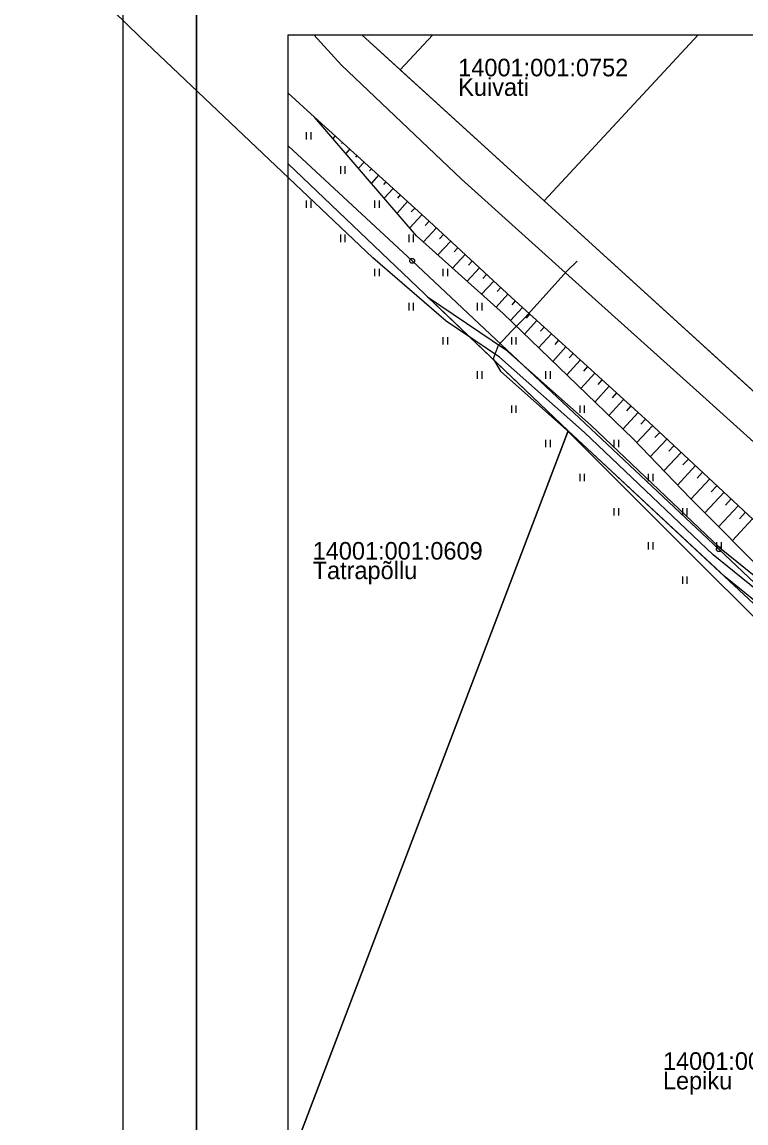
# Model space of a CAD drawing. Extents: x 567864 to 568657, y 6579839 to 6580994.
# Drawn here: x 568233.7 to 568307.8, y 6580491.9 to 6580604.7 of the extents above; entities that cross this region are included whole.
import ezdxf

# ---------------------------------------------------------------- set-up
doc = ezdxf.new("R2010")
doc.units = 0
for name, color, linetype in [('HALJASTUS', 7, 'Continuous'), ('KASUTUSALA', 7, 'Continuous'), ('MPKAABEL', 7, 'Continuous'), ('MPOHULIIN', 7, 'Continuous'), ('PIIR', 7, 'Continuous'), ('POST', 7, 'Continuous'), ('PR_SIDE', 7, 'Continuous'), ('RELJEEF', 7, 'Continuous'), ('TEE', 7, 'Continuous'), ('VORMISTUS_2', 7, 'Continuous')]:
    doc.layers.add(name, color=color, linetype=linetype)

msp = doc.modelspace()

# ---------------------------------------------------------------- linework, layer by layer
at = {"layer": 'HALJASTUS'}
for p, q in [((568262.77, 6580593.38), (568262.77, 6580592.62)), ((568263.23, 6580593.38), (568263.23, 6580592.62)), ((568266.27, 6580589.88), (568266.27, 6580589.12)), ((568266.73, 6580589.88), (568266.73, 6580589.12)), ((568262.77, 6580586.38), (568262.77, 6580585.62)), ((568263.23, 6580586.38), (568263.23, 6580585.62)), ((568269.77, 6580586.38), (568269.77, 6580585.62)), ((568270.23, 6580586.38), (568270.23, 6580585.62)), ((568266.27, 6580582.88), (568266.27, 6580582.12)), ((568266.73, 6580582.88), (568266.73, 6580582.12)), ((568273.27, 6580582.88), (568273.27, 6580582.12)), ((568273.73, 6580582.88), (568273.73, 6580582.12)), ((568269.77, 6580579.38), (568269.77, 6580578.62)), ((568270.23, 6580579.38), (568270.23, 6580578.62)), ((568276.77, 6580579.38), (568276.77, 6580578.62)), ((568277.23, 6580579.38), (568277.23, 6580578.62)), ((568273.27, 6580575.88), (568273.27, 6580575.12)), ((568273.73, 6580575.88), (568273.73, 6580575.12)), ((568280.27, 6580575.88), (568280.27, 6580575.12)), ((568280.73, 6580575.88), (568280.73, 6580575.12)), ((568276.77, 6580572.38), (568276.77, 6580571.62)), ((568277.23, 6580572.38), (568277.23, 6580571.62)), ((568283.77, 6580572.38), (568283.77, 6580571.62)), ((568284.23, 6580572.38), (568284.23, 6580571.62)), ((568280.27, 6580568.88), (568280.27, 6580568.12)), ((568280.73, 6580568.88), (568280.73, 6580568.12)), ((568287.27, 6580568.88), (568287.27, 6580568.12)), ((568287.73, 6580568.88), (568287.73, 6580568.12)), ((568283.77, 6580565.38), (568283.77, 6580564.62)), ((568284.23, 6580565.38), (568284.23, 6580564.62)), ((568290.77, 6580565.38), (568290.77, 6580564.62)), ((568291.23, 6580565.38), (568291.23, 6580564.62)), ((568287.27, 6580561.88), (568287.27, 6580561.12)), ((568287.73, 6580561.88), (568287.73, 6580561.12)), ((568294.27, 6580561.88), (568294.27, 6580561.12)), ((568294.73, 6580561.88), (568294.73, 6580561.12)), ((568290.77, 6580558.38), (568290.77, 6580557.62)), ((568291.23, 6580558.38), (568291.23, 6580557.62)), ((568297.77, 6580558.38), (568297.77, 6580557.62)), ((568298.23, 6580558.38), (568298.23, 6580557.62)), ((568294.27, 6580554.88), (568294.27, 6580554.12)), ((568294.73, 6580554.88), (568294.73, 6580554.12)), ((568301.27, 6580554.88), (568301.27, 6580554.12)), ((568301.73, 6580554.88), (568301.73, 6580554.12)), ((568297.77, 6580551.38), (568297.77, 6580550.62)), ((568298.23, 6580551.38), (568298.23, 6580550.62)), ((568304.77, 6580551.38), (568304.77, 6580550.62)), ((568305.23, 6580551.38), (568305.23, 6580550.62)), ((568301.27, 6580547.88), (568301.27, 6580547.12)), ((568301.73, 6580547.88), (568301.73, 6580547.12))]:
    msp.add_line(p, q, dxfattribs=at)
at = {"layer": 'KASUTUSALA'}
msp.add_lwpolyline([(568371.56, 6580487.01), (568366.82, 6580493.74), (568336.54, 6580520.89), (568334.37, 6580522.89), (568333.16, 6580524.02), (568322.19, 6580534.42), (568305.67, 6580547.79), (568289.57, 6580562.8), (568275.19, 6580576.52), (568283.17, 6580571.11), (568291.95, 6580563.33), (568305.08, 6580550.84), (568323.51, 6580535.93), (568334.54, 6580525.48), (568335.07, 6580524.98), (568344.93, 6580533.71), (568344.98, 6580533.67), (568346.42, 6580532.36), (568336.55, 6580523.61), (568337.05, 6580523.13), (568337.88, 6580522.37), (568368.32, 6580495.08), (568373.24, 6580488.09)], dxfattribs=at)
at = {"layer": 'MPKAABEL'}
msp.add_lwpolyline([(568290.51, 6580580.15), (568289.47, 6580579.17), (568285.16, 6580574.37), (568283.84, 6580573.07), (568282.41, 6580571.53), (568281.92, 6580570.15), (568282.67, 6580568.89), (568289.46, 6580562.85), (568299.87, 6580552.42), (568311.62, 6580540.71), (568323.73, 6580528.68), (568334.96, 6580518.16), (568345.24, 6580508.32), (568353.21, 6580500.74), (568358.87, 6580494.79), (568362.88, 6580490.81), (568367.26, 6580487.78), (568369.74, 6580485.8), (568369.72, 6580484.3), (568368.69, 6580483.14), (568367.08, 6580481.93), (568366.32, 6580481.93), (568366.01, 6580481.86)], dxfattribs=at)
at = {"layer": 'MPOHULIIN'}
msp.add_lwpolyline([(568335.69, 6580521.66), (568305, 6580550.67), (568273.62, 6580580.19), (568260.93, 6580591.97)], dxfattribs=at)
at = {"layer": 'PIIR'}
for points in [[(568268.46, 6580603.35), (568287.11, 6580586.34), (568330.81, 6580546.53), (568384.68, 6580497.48)], [(568275.73, 6580603.35), (568272.4, 6580599.76), (568268.46, 6580603.35)], [(568302.89, 6580603.35), (568287.11, 6580586.34), (568272.4, 6580599.76), (568275.73, 6580603.35)], [(568383.76, 6580603.35), (568370.95, 6580562.05), (568344.98, 6580533.67), (568287.11, 6580586.34), (568302.89, 6580603.35)], [(568384.68, 6580474.14), (568373.5, 6580484.56), (568289.57, 6580562.8), (568260.93, 6580590.14)], [(568260.93, 6580590.14), (568289.57, 6580562.8), (568260.93, 6580487.5)], [(568260.93, 6580487.5), (568289.57, 6580562.8), (568373.5, 6580484.56), (568310.3, 6580445.85)]]:
    msp.add_lwpolyline(points, dxfattribs=at)
at = {"layer": 'POST'}
for centre in [(568273.62, 6580580.19), (568305, 6580550.67)]:
    msp.add_circle(centre, 0.25, dxfattribs=at)
at = {"layer": 'PR_SIDE'}
msp.add_lwpolyline([(568372.77, 6580480.66), (568372.77, 6580480.66), (568372.77, 6580480.66), (568373.4, 6580481.36), (568374.25, 6580482.51), (568374.05, 6580484.04), (568373.82, 6580485.15), (568372.4, 6580487.55), (568367.57, 6580494.41), (568337.21, 6580521.63), (568335.06, 6580523.62), (568333.85, 6580524.75), (568322.86, 6580535.18), (568304.42, 6580550.09), (568291.27, 6580562.6), (568282.56, 6580570.32), (568277.09, 6580574.03), (568269.58, 6580580.5), (568245.73, 6580603.12), (568233.69, 6580614.91)], dxfattribs=at)
at = {"layer": 'RELJEEF'}
for p, q in [((568264.26, 6580594.34), (568264.19, 6580594.26)), ((568265, 6580593.66), (568264.95, 6580593.61)), ((568265.74, 6580592.99), (568265.5, 6580592.73)), ((568266.48, 6580592.32), (568266.38, 6580592.21)), ((568267.22, 6580591.65), (568266.81, 6580591.2)), ((568267.96, 6580590.97), (568267.81, 6580590.81)), ((568268.7, 6580590.3), (568268.13, 6580589.67)), ((568269.44, 6580589.63), (568269.24, 6580589.41)), ((568270.18, 6580588.96), (568269.44, 6580588.14)), ((568270.92, 6580588.28), (568270.67, 6580588.01)), ((568271.66, 6580587.61), (568270.75, 6580586.61)), ((568272.4, 6580586.94), (568272.1, 6580586.61)), ((568273.14, 6580586.27), (568272.07, 6580585.08)), ((568274.62, 6580584.92), (568273.38, 6580583.56)), ((568273.88, 6580585.59), (568273.53, 6580585.21)), ((568276.09, 6580583.57), (568274.76, 6580582.13)), ((568275.36, 6580584.25), (568274.96, 6580583.82)), ((568276.83, 6580582.89), (568276.43, 6580582.46)), ((568277.56, 6580582.21), (568276.25, 6580580.8)), ((568278.29, 6580581.53), (568277.9, 6580581.11)), ((568279.03, 6580580.85), (568277.74, 6580579.46)), ((568279.76, 6580580.17), (568279.38, 6580579.76)), ((568280.49, 6580579.49), (568279.23, 6580578.12)), ((568281.96, 6580578.13), (568280.72, 6580576.79)), ((568281.22, 6580578.81), (568280.85, 6580578.4)), ((568283.42, 6580576.77), (568282.21, 6580575.45)), ((568282.69, 6580577.45), (568282.32, 6580577.05)), ((568284.16, 6580576.09), (568283.8, 6580575.7)), ((568284.9, 6580575.42), (568283.68, 6580574.08)), ((568285.64, 6580574.75), (568285.27, 6580574.34)), ((568286.38, 6580574.07), (568285.12, 6580572.69)), ((568287.12, 6580573.4), (568286.74, 6580572.98)), ((568287.86, 6580572.73), (568286.56, 6580571.3)), ((568289.34, 6580571.38), (568288, 6580569.9)), ((568288.6, 6580572.06), (568288.2, 6580571.62)), ((568290.82, 6580570.04), (568289.44, 6580568.51)), ((568290.08, 6580570.71), (568289.67, 6580570.26)), ((568291.56, 6580569.37), (568291.14, 6580568.9)), ((568292.3, 6580568.69), (568290.87, 6580567.12)), ((568293.04, 6580568.02), (568292.61, 6580567.54)), ((568293.78, 6580567.35), (568292.31, 6580565.73)), ((568294.52, 6580566.68), (568294.07, 6580566.18)), ((568295.26, 6580566), (568293.75, 6580564.34)), ((568296.74, 6580564.66), (568295.19, 6580562.95)), ((568296, 6580565.33), (568295.54, 6580564.82)), ((568298.22, 6580563.31), (568296.59, 6580561.56)), ((568297.48, 6580563.98), (568297.01, 6580563.47)), ((568298.95, 6580562.63), (568298.45, 6580562.09)), ((568299.68, 6580561.94), (568297.98, 6580560.12)), ((568300.41, 6580561.26), (568299.89, 6580560.7)), ((568301.14, 6580560.58), (568299.37, 6580558.68)), ((568301.88, 6580559.9), (568301.33, 6580559.32)), ((568302.61, 6580559.22), (568300.76, 6580557.23)), ((568304.07, 6580557.86), (568302.15, 6580555.79)), ((568303.34, 6580558.54), (568302.77, 6580557.93)), ((568305.54, 6580556.49), (568303.56, 6580554.38)), ((568304.8, 6580557.17), (568304.22, 6580556.55)), ((568306.27, 6580555.81), (568305.67, 6580555.17)), ((568307, 6580555.13), (568304.98, 6580552.96)), ((568307.73, 6580554.45), (568307.12, 6580553.79)), ((568308.46, 6580553.77), (568306.39, 6580551.54))]:
    msp.add_line(p, q, dxfattribs=at)
msp.add_lwpolyline([(568310.42, 6580547.5), (568302.1, 6580555.85), (568296.22, 6580561.96), (568282.93, 6580574.8), (568274.07, 6580582.75), (568263.63, 6580594.9)], dxfattribs=at)
at = {"layer": 'TEE'}
for points in [[(568384.68, 6580492.57), (568380.78, 6580496.19), (568368.5, 6580507.85), (568359.52, 6580516.22), (568354.33, 6580521.19), (568352.36, 6580522.29), (568341.44, 6580532.14), (568331.96, 6580540.8), (568322.6, 6580549.12), (568312.08, 6580558.49), (568303.36, 6580566.33), (568291.02, 6580577.44), (568278.67, 6580588.56), (568266.39, 6580600.24), (568263.55, 6580603.35)], [(568376.41, 6580491.21), (568374.68, 6580493.82), (568369.68, 6580498.66), (568354.03, 6580512.91), (568337.06, 6580528.03), (568327.84, 6580536.25), (568318.37, 6580544.73), (568308.51, 6580553.72), (568297.84, 6580563.66), (568283.77, 6580576.45), (568275.34, 6580584.27), (568263.63, 6580594.9), (568260.93, 6580597.38)]]:
    msp.add_lwpolyline(points, dxfattribs=at)
at = {"layer": 'VORMISTUS_2'}
for points in [[(568244.05, 6580640.85), (568401.55, 6580640.85), (568401.55, 6580418.1), (568244.05, 6580418.1)], [(568251.55, 6580426.35), (568394.05, 6580426.35), (568394.05, 6580632.6), (568251.55, 6580632.6)], [(568251.55, 6580632.6), (568394.05, 6580632.6), (568394.05, 6580426.35), (568251.55, 6580426.35)], [(568384.68, 6580445.85), (568260.93, 6580445.85), (568260.93, 6580603.35), (568384.68, 6580603.35)]]:
    msp.add_lwpolyline(points, close=True, dxfattribs=at)

# ---------------------------------------------------------------- texts
at = {"layer": 'PIIR'}
for s, p in [('14001:001:0752', (568278.33, 6580599.09)), ('Kuivati', (568278.33, 6580597.09)), ('14001:001:0609', (568263.43, 6580549.6)), ('Tatrapõllu', (568263.43, 6580547.6)), ('14001:001:0114', (568299.28, 6580497.35)), ('Lepiku', (568299.28, 6580495.35))]:
    msp.add_text(s, height=1.8, dxfattribs=at).set_placement(p)

doc.saveas('drawing.dxf')
